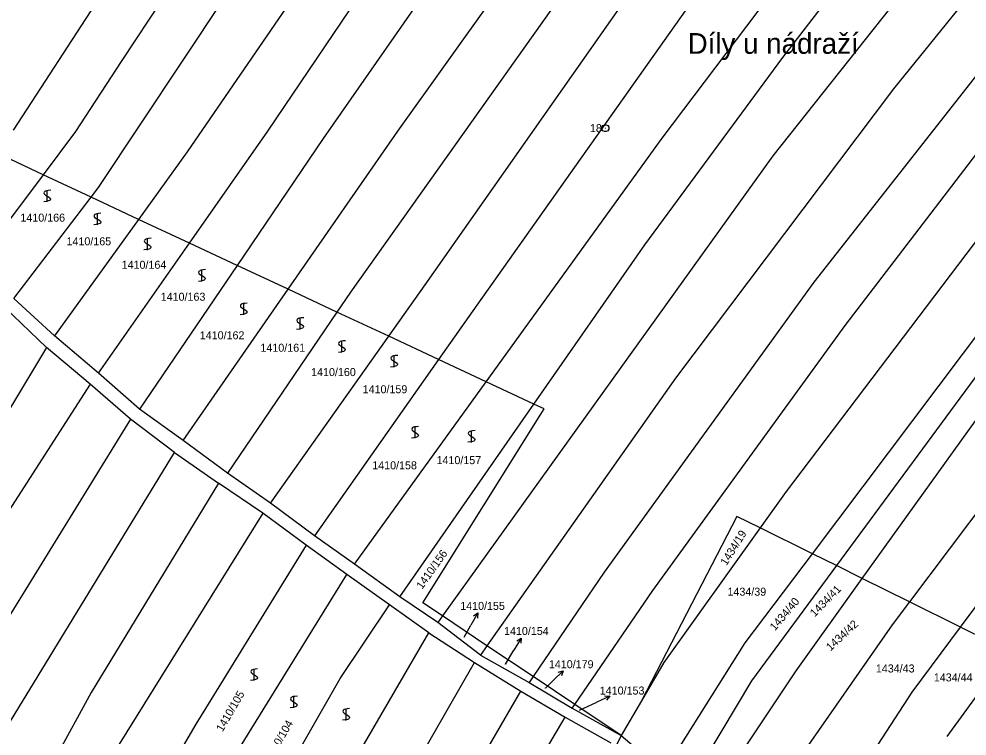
# Model space of a CAD drawing. Extents: x -580630 to -576196, y -1189024 to -1183567.
# Drawn here: x -578714.2 to -578512.9, y -1187051.1 to -1186898.8 of the extents above; entities that cross this region are included whole.
import ezdxf

# ---------------------------------------------------------------- set-up
doc = ezdxf.new("R2010")
doc.units = 0
for name, color, linetype in [('Vrstva 1', 7, 'Continuous'), ('Vrstva 15', 7, 'Continuous'), ('Vrstva 16', 7, 'Continuous'), ('Vrstva 17', 7, 'Continuous'), ('Vrstva 18', 7, 'Continuous'), ('Vrstva 24', 7, 'Continuous'), ('Vrstva 25', 7, 'Continuous'), ('Vrstva 6', 7, 'Continuous')]:
    doc.layers.add(name, color=color, linetype=linetype)

msp = doc.modelspace()

# ---------------------------------------------------------------- linework, layer by layer
at = {"layer": 'Vrstva 1'}
for p, q in [((-578709.06, -1186931.85), (-578718.98, -1186927.21)), ((-578698.87, -1186936.62), (-578709.06, -1186931.85)), ((-578688.79, -1186941.33), (-578698.87, -1186936.62)), ((-578677.99, -1186946.38), (-578688.79, -1186941.33)), ((-578667.87, -1186951.11), (-578677.99, -1186946.38)), ((-578657.03, -1186956.18), (-578667.87, -1186951.11)), ((-578646.67, -1186961.03), (-578657.03, -1186956.18)), ((-578635.67, -1186966.17), (-578646.67, -1186961.03)), ((-578625.09, -1186971.12), (-578635.67, -1186966.17)), ((-578614.97, -1186975.85), (-578625.09, -1186971.12)), ((-578604.86, -1186980.58), (-578614.97, -1186975.85)), ((-578628.45, -1187022.79), (-578602.69, -1186981.6)), ((-578602.69, -1186981.6), (-578604.86, -1186980.58)), ((-578561.78, -1187004.43), (-578582.05, -1187043.62)), ((-578556.86, -1187006.87), (-578561.78, -1187004.43)), ((-578545.74, -1187012.37), (-578556.86, -1187006.87)), ((-578540.65, -1187014.89), (-578545.74, -1187012.37)), ((-578535.14, -1187017.62), (-578540.65, -1187014.89)), ((-578525.13, -1187022.58), (-578535.14, -1187017.62)), ((-578624.28, -1187025.58), (-578628.45, -1187022.79)), ((-578514.29, -1187027.95), (-578525.13, -1187022.58)), ((-578614.83, -1187031.91), (-578624.28, -1187025.58)), ((-578504.01, -1187033.04), (-578514.29, -1187027.95)), ((-578605.04, -1187038.47), (-578614.83, -1187031.91)), ((-578596.19, -1187044.39), (-578605.04, -1187038.47)), ((-578586.36, -1187050.97), (-578596.19, -1187044.39)), ((-578582.05, -1187043.62), (-578586.36, -1187050.97)), ((-578586.36, -1187050.97), (-578587.46, -1187053.29))]:
    msp.add_line(p, q, dxfattribs=at)
at = {"layer": 'Vrstva 16'}
for p, q in [((-578616.775, -1187024.938), (-578618.25, -1187027.55)), ((-578619.66, -1187030.05), (-578618.25, -1187027.55)), ((-578607.567, -1187030.267), (-578609.11, -1187032.84)), ((-578610.9, -1187035.82), (-578609.11, -1187032.84)), ((-578598.634, -1187037.203), (-578600.77, -1187039.31)), ((-578602.41, -1187040.92), (-578600.77, -1187039.31)), ((-578595.2, -1187045.59), (-578591.48, -1187043.86)), ((-578588.76, -1187042.594), (-578591.48, -1187043.86))]:
    msp.add_line(p, q, dxfattribs=at)
for points in [[(-578617.702, -1187025.563), (-578616.775, -1187024.938), (-578616.831, -1187026.055)], [(-578608.51, -1187030.868), (-578607.567, -1187030.267), (-578607.653, -1187031.382)], [(-578599.697, -1187037.549), (-578598.634, -1187037.203), (-578598.995, -1187038.261)], [(-578589.878, -1187042.563), (-578588.76, -1187042.594), (-578589.456, -1187043.469)]]:
    msp.add_lwpolyline(points, dxfattribs=at)
at = {"layer": 'Vrstva 24'}
msp.add_line((-578589.76, -1186921.96), (-578589.66, -1186921.96), dxfattribs=at)
msp.add_lwpolyline([(-578589.52, -1186921.24), (-578589.18, -1186921.43), (-578588.99, -1186921.77), (-578588.99, -1186922.16), (-578589.18, -1186922.5), (-578589.52, -1186922.69), (-578589.91, -1186922.69), (-578590.25, -1186922.5), (-578590.44, -1186922.16), (-578590.44, -1186921.77), (-578590.25, -1186921.43), (-578589.91, -1186921.24)], close=True, dxfattribs=at)
at = {"layer": 'Vrstva 25'}
for points in [[(-578707.44, -1186935.14), (-578707.95, -1186935.2), (-578708.3, -1186935.25), (-578708.54, -1186935.33), (-578708.72, -1186935.44), (-578708.84, -1186935.53), (-578708.89, -1186935.7), (-578708.84, -1186935.93), (-578708.45, -1186936.25), (-578707.89, -1186936.56), (-578707.54, -1186936.83), (-578707.47, -1186937.03), (-578707.54, -1186937.23), (-578707.7, -1186937.36), (-578707.89, -1186937.43), (-578708.42, -1186937.56), (-578708.94, -1186937.63)], [(-578708.19, -1186937.64), (-578708.19, -1186936.37), (-578708.19, -1186935.14)], [(-578696.79, -1186940.02), (-578697.3, -1186940.08), (-578697.65, -1186940.13), (-578697.89, -1186940.21), (-578698.07, -1186940.32), (-578698.19, -1186940.41), (-578698.24, -1186940.58), (-578698.19, -1186940.81), (-578697.8, -1186941.13), (-578697.24, -1186941.44), (-578696.89, -1186941.71), (-578696.82, -1186941.91), (-578696.89, -1186942.11), (-578697.05, -1186942.24), (-578697.24, -1186942.31), (-578697.77, -1186942.44), (-578698.29, -1186942.51)], [(-578697.54, -1186942.52), (-578697.54, -1186941.25), (-578697.54, -1186940.02)], [(-578686.14, -1186945.35), (-578686.65, -1186945.41), (-578687, -1186945.46), (-578687.24, -1186945.54), (-578687.42, -1186945.65), (-578687.54, -1186945.74), (-578687.59, -1186945.91), (-578687.54, -1186946.14), (-578687.15, -1186946.46), (-578686.59, -1186946.77), (-578686.24, -1186947.04), (-578686.17, -1186947.24), (-578686.24, -1186947.44), (-578686.4, -1186947.57), (-578686.59, -1186947.64), (-578687.12, -1186947.77), (-578687.64, -1186947.84)], [(-578686.89, -1186947.85), (-578686.89, -1186946.58), (-578686.89, -1186945.35)], [(-578674.6, -1186952.01), (-578675.11, -1186952.07), (-578675.46, -1186952.12), (-578675.7, -1186952.2), (-578675.88, -1186952.31), (-578676, -1186952.4), (-578676.05, -1186952.57), (-578676, -1186952.8), (-578675.61, -1186953.12), (-578675.05, -1186953.43), (-578674.7, -1186953.7), (-578674.63, -1186953.9), (-578674.7, -1186954.1), (-578674.86, -1186954.23), (-578675.05, -1186954.3), (-578675.58, -1186954.43), (-578676.1, -1186954.5)], [(-578675.35, -1186954.51), (-578675.35, -1186953.24), (-578675.35, -1186952.01)], [(-578665.73, -1186959.12), (-578666.24, -1186959.18), (-578666.59, -1186959.23), (-578666.83, -1186959.31), (-578667.01, -1186959.42), (-578667.13, -1186959.51), (-578667.18, -1186959.68), (-578667.13, -1186959.91), (-578666.74, -1186960.23), (-578666.18, -1186960.54), (-578665.83, -1186960.81), (-578665.76, -1186961.01), (-578665.83, -1186961.21), (-578665.99, -1186961.34), (-578666.18, -1186961.41), (-578666.71, -1186961.54), (-578667.23, -1186961.61)], [(-578666.48, -1186961.62), (-578666.48, -1186960.35), (-578666.48, -1186959.12)], [(-578653.74, -1186962.22), (-578654.25, -1186962.28), (-578654.6, -1186962.33), (-578654.84, -1186962.41), (-578655.02, -1186962.52), (-578655.14, -1186962.61), (-578655.19, -1186962.78), (-578655.14, -1186963.01), (-578654.75, -1186963.33), (-578654.19, -1186963.64), (-578653.84, -1186963.91), (-578653.77, -1186964.11), (-578653.84, -1186964.31), (-578654, -1186964.44), (-578654.19, -1186964.51), (-578654.72, -1186964.64), (-578655.24, -1186964.71)], [(-578654.49, -1186964.72), (-578654.49, -1186963.45), (-578654.49, -1186962.22)], [(-578644.87, -1186967.11), (-578645.38, -1186967.17), (-578645.73, -1186967.22), (-578645.97, -1186967.3), (-578646.15, -1186967.41), (-578646.27, -1186967.5), (-578646.32, -1186967.67), (-578646.27, -1186967.9), (-578645.88, -1186968.22), (-578645.32, -1186968.53), (-578644.97, -1186968.8), (-578644.9, -1186969), (-578644.97, -1186969.2), (-578645.13, -1186969.33), (-578645.32, -1186969.4), (-578645.85, -1186969.53), (-578646.37, -1186969.6)], [(-578645.62, -1186969.61), (-578645.62, -1186968.34), (-578645.62, -1186967.11)], [(-578633.78, -1186970.22), (-578634.29, -1186970.28), (-578634.64, -1186970.33), (-578634.88, -1186970.41), (-578635.06, -1186970.52), (-578635.18, -1186970.61), (-578635.23, -1186970.78), (-578635.18, -1186971.01), (-578634.79, -1186971.33), (-578634.23, -1186971.64), (-578633.88, -1186971.91), (-578633.81, -1186972.11), (-578633.88, -1186972.31), (-578634.04, -1186972.44), (-578634.23, -1186972.51), (-578634.76, -1186972.64), (-578635.28, -1186972.71)], [(-578634.53, -1186972.72), (-578634.53, -1186971.45), (-578634.53, -1186970.22)], [(-578629.34, -1186985.31), (-578629.85, -1186985.37), (-578630.2, -1186985.42), (-578630.44, -1186985.5), (-578630.62, -1186985.61), (-578630.74, -1186985.7), (-578630.79, -1186985.87), (-578630.74, -1186986.1), (-578630.35, -1186986.42), (-578629.79, -1186986.73), (-578629.44, -1186987), (-578629.37, -1186987.2), (-578629.44, -1186987.4), (-578629.6, -1186987.53), (-578629.79, -1186987.6), (-578630.32, -1186987.73), (-578630.84, -1186987.8)], [(-578630.09, -1186987.81), (-578630.09, -1186986.54), (-578630.09, -1186985.31)], [(-578617.36, -1186986.2), (-578617.87, -1186986.26), (-578618.22, -1186986.31), (-578618.46, -1186986.39), (-578618.64, -1186986.5), (-578618.76, -1186986.59), (-578618.81, -1186986.76), (-578618.76, -1186986.99), (-578618.37, -1186987.31), (-578617.81, -1186987.62), (-578617.46, -1186987.89), (-578617.39, -1186988.09), (-578617.46, -1186988.29), (-578617.62, -1186988.42), (-578617.81, -1186988.49), (-578618.34, -1186988.62), (-578618.86, -1186988.69)], [(-578618.11, -1186988.7), (-578618.11, -1186987.43), (-578618.11, -1186986.2)], [(-578663.51, -1187036.81), (-578664.02, -1187036.87), (-578664.37, -1187036.92), (-578664.61, -1187037), (-578664.79, -1187037.11), (-578664.91, -1187037.2), (-578664.96, -1187037.37), (-578664.91, -1187037.6), (-578664.52, -1187037.92), (-578663.96, -1187038.23), (-578663.61, -1187038.5), (-578663.54, -1187038.7), (-578663.61, -1187038.9), (-578663.77, -1187039.03), (-578663.96, -1187039.1), (-578664.49, -1187039.23), (-578665.01, -1187039.3)], [(-578664.26, -1187039.31), (-578664.26, -1187038.04), (-578664.26, -1187036.81)], [(-578655.08, -1187042.59), (-578655.59, -1187042.65), (-578655.94, -1187042.7), (-578656.18, -1187042.78), (-578656.36, -1187042.89), (-578656.48, -1187042.98), (-578656.53, -1187043.15), (-578656.48, -1187043.38), (-578656.09, -1187043.7), (-578655.53, -1187044.01), (-578655.18, -1187044.28), (-578655.11, -1187044.48), (-578655.18, -1187044.68), (-578655.34, -1187044.81), (-578655.53, -1187044.88), (-578656.06, -1187045.01), (-578656.58, -1187045.08)], [(-578655.83, -1187045.09), (-578655.83, -1187043.82), (-578655.83, -1187042.59)], [(-578643.98, -1187045.25), (-578644.49, -1187045.31), (-578644.84, -1187045.36), (-578645.08, -1187045.44), (-578645.26, -1187045.55), (-578645.38, -1187045.64), (-578645.43, -1187045.81), (-578645.38, -1187046.04), (-578644.99, -1187046.36), (-578644.43, -1187046.67), (-578644.08, -1187046.94), (-578644.01, -1187047.14), (-578644.08, -1187047.34), (-578644.24, -1187047.47), (-578644.43, -1187047.54), (-578644.96, -1187047.67), (-578645.48, -1187047.74)], [(-578644.73, -1187047.75), (-578644.73, -1187046.48), (-578644.73, -1187045.25)]]:
    msp.add_lwpolyline(points, dxfattribs=at)
at = {"layer": 'Vrstva 6'}
for p, q in [((-578620.54, -1186842.52), (-578678.45, -1186927)), ((-578633.72, -1186922.59), (-578576.18, -1186841.62)), ((-578650.73, -1186844.42), (-578692.46, -1186907.79)), ((-578577.61, -1186924.1), (-578517.97, -1186844.99)), ((-578477.61, -1186850.76), (-578528.51, -1186913.58)), ((-578599.68, -1186852.33), (-578649.59, -1186924.19)), ((-578552.05, -1186906.96), (-578513.99, -1186857.61)), ((-578661.37, -1186922.62), (-578618.89, -1186859.74)), ((-578508.59, -1186870.3), (-578554.11, -1186927.86)), ((-578481.85, -1186873.69), (-578545.47, -1186954.67)), ((-578715.31, -1186922.37), (-578686.66, -1186878.15)), ((-578697.31, -1186934.57), (-578667.17, -1186889.15)), ((-578599.05, -1186893.77), (-578643.79, -1186956.79)), ((-578627.94, -1186955.26), (-578586.18, -1186895.79)), ((-578572.77, -1186897.05), (-578616.96, -1186959.58)), ((-578581.32, -1186946.73), (-578552.05, -1186906.96)), ((-578692.46, -1186907.79), (-578702.19, -1186922.68)), ((-578538.79, -1186963.86), (-578500.08, -1186913.23)), ((-578528.51, -1186913.58), (-578574.79, -1186975.09)), ((-578702.19, -1186922.68), (-578709.06, -1186931.85)), ((-578677.99, -1186946.38), (-578661.37, -1186922.62)), ((-578657.03, -1186956.18), (-578633.72, -1186922.59)), ((-578649.59, -1186924.19), (-578667.87, -1186951.11)), ((-578614.97, -1186975.85), (-578577.61, -1186924.1)), ((-578678.45, -1186927), (-578688.79, -1186941.33)), ((-578554.11, -1186927.86), (-578624.28, -1187025.58)), ((-578498.99, -1186930.06), (-578551.34, -1186999.14)), ((-578709.06, -1186931.85), (-578723.22, -1186950.76)), ((-578698.87, -1186936.62), (-578697.31, -1186934.57)), ((-578715.26, -1186958.14), (-578698.87, -1186936.62)), ((-578688.79, -1186941.33), (-578706.61, -1186966.04)), ((-578464.58, -1186941.91), (-578525.13, -1187022.58)), ((-578697.32, -1186974.01), (-578677.99, -1186946.38)), ((-578604.86, -1186980.58), (-578581.32, -1186946.73)), ((-578545.74, -1187012.37), (-578497.5, -1186948.2)), ((-578492.22, -1186949.09), (-578540.65, -1187014.89)), ((-578667.87, -1186951.11), (-578688.62, -1186981.68)), ((-578635.67, -1186966.17), (-578627.94, -1186955.26)), ((-578545.47, -1186954.67), (-578589.97, -1187016.28)), ((-578679.34, -1186988.32), (-578657.03, -1186956.18)), ((-578643.79, -1186956.79), (-578646.67, -1186961.03)), ((-578706.61, -1186966.04), (-578715.26, -1186958.14)), ((-578616.96, -1186959.58), (-578625.09, -1186971.12)), ((-578717.18, -1186960.07), (-578708.36, -1186968.52)), ((-578646.67, -1186961.03), (-578669.9, -1186995.25)), ((-578579.6, -1187020.17), (-578538.79, -1186963.86)), ((-578697.32, -1186974.01), (-578706.61, -1186966.04)), ((-578660.76, -1187001.59), (-578635.67, -1186966.17)), ((-578708.36, -1186968.52), (-578741.4, -1187023.71)), ((-578699.07, -1186976.32), (-578708.36, -1186968.52)), ((-578625.09, -1186971.12), (-578651.47, -1187008.53)), ((-578514.29, -1187027.95), (-578472.1, -1186971)), ((-578688.62, -1186981.68), (-578697.32, -1186974.01)), ((-578642.92, -1187014.57), (-578614.97, -1186975.85)), ((-578574.79, -1186975.09), (-578614.83, -1187031.91)), ((-578699.07, -1186976.32), (-578717.66, -1187005.28)), ((-578690.48, -1186983.75), (-578699.07, -1186976.32)), ((-578679.34, -1186988.32), (-578688.62, -1186981.68)), ((-578633.3, -1187021.49), (-578604.86, -1186980.58)), ((-578690.48, -1186983.75), (-578725.62, -1187040.75)), ((-578681.19, -1186990.89), (-578690.48, -1186983.75)), ((-578535.14, -1187017.62), (-578511.11, -1186984.16)), ((-578669.9, -1186995.25), (-578679.34, -1186988.32)), ((-578717.54, -1187050.45), (-578681.19, -1186990.89)), ((-578681.19, -1186990.89), (-578671.8, -1186997.37)), ((-578660.76, -1187001.59), (-578669.9, -1186995.25)), ((-578671.8, -1186997.37), (-578698.86, -1187041.81)), ((-578662.4, -1187003.72), (-578671.8, -1186997.37)), ((-578551.34, -1186999.14), (-578556.86, -1187006.87)), ((-578651.47, -1187008.53), (-578660.76, -1187001.59)), ((-578662.4, -1187003.72), (-578692.88, -1187052.84)), ((-578653.2, -1187010.55), (-578662.4, -1187003.72)), ((-578556.86, -1187006.87), (-578577.25, -1187035.44)), ((-578642.92, -1187014.57), (-578651.47, -1187008.53)), ((-578653.2, -1187010.55), (-578676.65, -1187048.55)), ((-578644.61, -1187016.76), (-578653.2, -1187010.55)), ((-578559.98, -1187031.31), (-578545.74, -1187012.37)), ((-578633.3, -1187021.49), (-578642.92, -1187014.57)), ((-578540.65, -1187014.89), (-578558.66, -1187039.36)), ((-578670.1, -1187058.05), (-578644.61, -1187016.76)), ((-578635.55, -1187023.21), (-578644.61, -1187016.76)), ((-578589.97, -1187016.28), (-578605.04, -1187038.47)), ((-578549.22, -1187037.23), (-578535.14, -1187017.62)), ((-578596.19, -1187044.39), (-578579.6, -1187020.17)), ((-578625.28, -1187026.98), (-578633.3, -1187021.49)), ((-578645.98, -1187038.86), (-578635.55, -1187023.21)), ((-578627.18, -1187029.17), (-578635.55, -1187023.21)), ((-578525.13, -1187022.58), (-578528.82, -1187027.49)), ((-578624.28, -1187025.58), (-578625.28, -1187026.98)), ((-578616.23, -1187033.89), (-578625.28, -1187026.98)), ((-578528.82, -1187027.49), (-578547.69, -1187054.57)), ((-578524.53, -1187041.76), (-578514.29, -1187027.95)), ((-578651.77, -1187071.45), (-578627.18, -1187029.17)), ((-578627.18, -1187029.17), (-578617.5, -1187035.48)), ((-578614.83, -1187031.91), (-578616.23, -1187033.89)), ((-578577.25, -1187058.61), (-578559.98, -1187031.31)), ((-578616.23, -1187033.89), (-578605.87, -1187039.69)), ((-578504.01, -1187033.04), (-578517.23, -1187051.2)), ((-578646.13, -1187085.34), (-578617.5, -1187035.48)), ((-578617.5, -1187035.48), (-578607.65, -1187041.52)), ((-578577.25, -1187035.44), (-578582.05, -1187043.62)), ((-578568.41, -1187066.01), (-578549.22, -1187037.23)), ((-578666.02, -1187073.73), (-578645.98, -1187038.86)), ((-578605.04, -1187038.47), (-578605.87, -1187039.69)), ((-578605.87, -1187039.69), (-578596.73, -1187045.18)), ((-578558.66, -1187039.36), (-578572.37, -1187062.27)), ((-578698.86, -1187041.81), (-578713.29, -1187068.13)), ((-578632.08, -1187083.58), (-578607.65, -1187041.52)), ((-578607.65, -1187041.52), (-578598.2, -1187047.04)), ((-578550.11, -1187080.79), (-578524.53, -1187041.76)), ((-578596.73, -1187045.18), (-578596.19, -1187044.39)), ((-578596.73, -1187045.18), (-578586.36, -1187050.97)), ((-578616.36, -1187077.77), (-578598.2, -1187047.04)), ((-578598.2, -1187047.04), (-578588.5, -1187052.51)), ((-578676.65, -1187048.55), (-578693.13, -1187076.88)), ((-578586.36, -1187050.97), (-578577.25, -1187058.61))]:
    msp.add_line(p, q, dxfattribs=at)

# ---------------------------------------------------------------- texts
at = {"layer": 'Vrstva 15'}
msp.add_text('Díly u nádraží', height=4.4, dxfattribs=at).set_placement((-578572.221, -1186906.17))
at = {"layer": 'Vrstva 16'}
for s, p in [('1410/155', (-578620.507, -1187024.29)), ('1410/154', (-578611.201, -1187029.62)), ('1410/179', (-578601.684, -1187036.68)), ('1410/153', (-578590.878, -1187042.27))]:
    msp.add_text(s, height=1.7, dxfattribs=at).set_placement(p)
at = {"layer": 'Vrstva 17'}
msp.add_text('18', height=1.7, dxfattribs=at).set_placement((-578592.974, -1186922.81))
at = {"layer": 'Vrstva 18'}
for s, height, p in [('1410/166', 1.7, (-578713.874, -1186941.82)), ('1410/165', 1.7, (-578704.091, -1186946.85)), ('1410/164', 1.7, (-578692.384, -1186951.83)), ('1410/163', 1.7, (-578684.091, -1186958.62)), ('1410/162', 1.7, (-578675.797, -1186966.81)), ('1410/161', 1.7, (-578662.916, -1186969.45)), ('1410/160', 1.7, (-578652.16, -1186974.62)), ('1410/159', 1.7, (-578641.221, -1186978.27)), ('1410/157', 1.7, (-578625.53, -1186993.33)), ('1410/158', 1.7, (-578639.181, -1186994.43)), ('1434/39', 1.7, (-578563.768, -1187021.27)), ('1410/155', 0.1, (-578619.929, -1187030.05)), ('1410/154', 0.1, (-578611.167, -1187035.82)), ('1434/43', 1.7, (-578532.268, -1187037.58)), ('1434/44', 1.7, (-578519.961, -1187039.48)), ('1410/179', 0.1, (-578602.671, -1187040.92)), ('1410/153', 0.1, (-578595.472, -1187045.59))]:
    msp.add_text(s, height=height, dxfattribs=at).set_placement(p)
for s, rotation, p in [('1434/19', 57.98333, (-578563.978, -1187015.013)), ('1410/156', 54.71747, (-578628.597, -1187020.038)), ('1434/41', 45.32096, (-578545.255, -1187025.888)), ('1434/40', 49.67544, (-578553.682, -1187028.84)), ('1434/42', 42.79995, (-578541.893, -1187033.112)), ('1410/105', 59.98868, (-578670.959, -1187050.316)), ('1410/104', 59.7022, (-578660.695, -1187056.534))]:
    msp.add_text(s, height=1.7, rotation=rotation, dxfattribs=at).set_placement(p)

doc.saveas('drawing.dxf')
